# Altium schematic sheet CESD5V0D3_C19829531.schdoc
size 127 x 101 mm
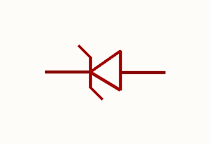
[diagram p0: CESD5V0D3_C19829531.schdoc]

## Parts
U?  cesd5v0d3_c19829531  [SOD-323_L1.7-W1.3-LS2.5-RD-1]  (value not drawn)

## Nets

Not connected (* = marked no-connect by the designer): U? 1 2

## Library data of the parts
U? = cesd5v0d3_c19829531: 极性:单向;反向截止电压(Vrwm):5V;最大钳位电压:20V;峰值脉冲电流(Ipp):10A;峰值脉冲功率(Ppp):200W;击穿电压:6V;; Manufacturer: TECH PUBLIC(台舟); AddInBom: yes; ModelId: 237a61d9b23c40859b870f08f1510208; ModelTransform: 98.425,49.2125,0,0,0,0,0,0,0; polarity: 单向; Reverse Stand-Off Voltage (Vrwm): 5V; Maximum Clamping Voltage: 20V; Peak Pulse Current (Ipp): 10A; Peak Pulse Power Dissipation (Ppp): 200W; Breakdown Voltage: 6V; Reverse Leakage Current (Ir): 500nA; Number of Lines: 单路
